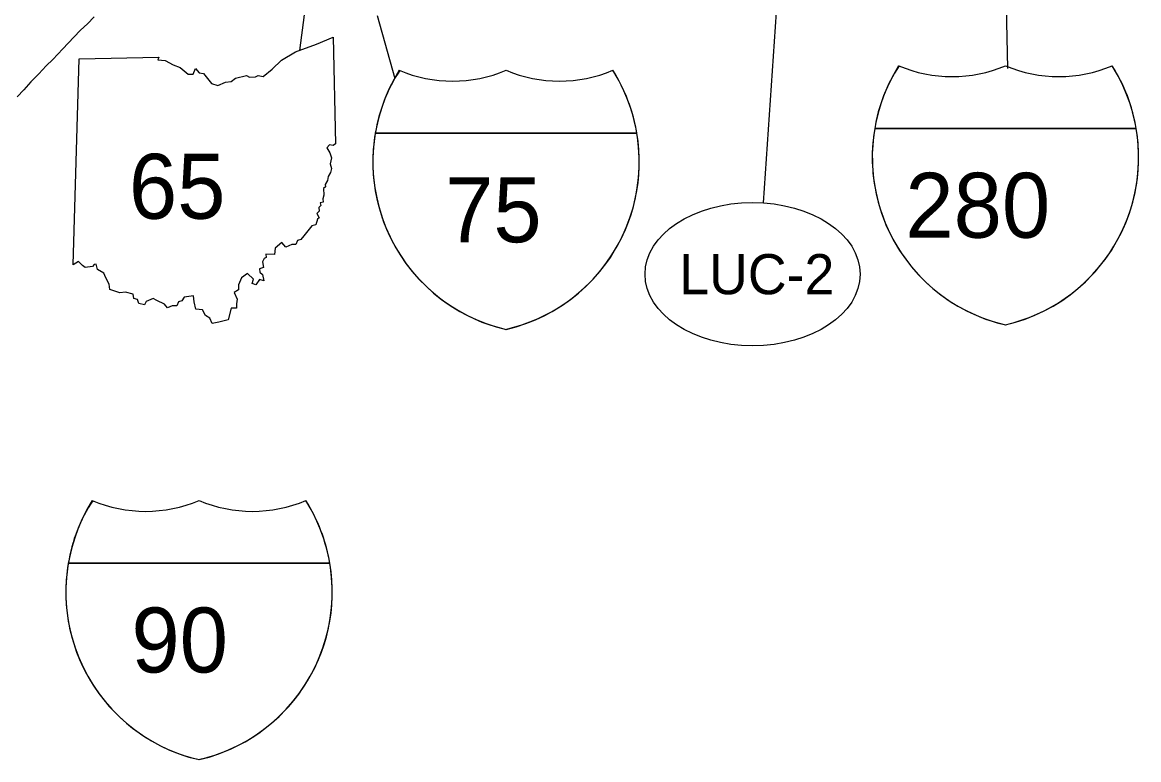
# Model space of a CAD drawing. Extents: x 0 to 750, y 0 to 507.
# Drawn here: x 327.4 to 405.3, y 183.7 to 235.1 of the extents above; entities that cross this region are included whole.
import ezdxf

# ---------------------------------------------------------------- set-up
doc = ezdxf.new("R2010")
doc.units = 0
for name, color, linetype in [('DV_X_Corp_Line', 7, 'Continuous'), ('GM_X_County', 7, 'Continuous'), ('GM_X_Interstate_Route', 7, 'Continuous'), ('GM_X_State_Route', 7, 'Continuous'), ('SH_Data', 7, 'Continuous')]:
    doc.layers.add(name, color=color, linetype=linetype)

msp = doc.modelspace()

# ---------------------------------------------------------------- linework, layer by layer
at = {"layer": 'DV_X_Corp_Line'}
msp.add_lwpolyline([(332.377, 235.528), (331.917, 235.045), (331.423, 234.597), (330.964, 234.113), (330.193, 233.304), (329.498, 232.548), (329.044, 232.12), (328.518, 231.557), (327.972, 231.005), (327.486, 230.432), (327.021, 229.948)], dxfattribs=at)
at = {"layer": 'GM_X_County'}
msp.add_lwpolyline([(332.377, 235.528), (331.917, 235.045), (331.423, 234.597), (330.964, 234.113), (330.193, 233.304), (329.498, 232.548), (329.044, 232.12), (328.518, 231.557), (327.972, 231.005), (327.486, 230.432), (327.021, 229.948)], dxfattribs=at)
at = {"layer": 'GM_X_Interstate_Route'}
for p, q in [((352.129, 235.628), (353.35, 231.223)), ((330.932, 218.25), (331.334, 232.613)), ((330.932, 218.25), (331.334, 232.613)), ((352, 227.428), (370.243, 227.428)), ((370.243, 227.428), (352, 227.428)), ((370.243, 227.428), (352, 227.428)), ((386.836, 227.744), (405.08, 227.744)), ((405.08, 227.744), (386.836, 227.744)), ((405.08, 227.744), (386.836, 227.744)), ((330.582, 197.435), (348.826, 197.435)), ((348.826, 197.435), (330.582, 197.435)), ((348.826, 197.435), (330.582, 197.435))]:
    msp.add_line(p, q, dxfattribs=at)
for points in [[(396.112, 231.926), (396.028, 236.226), (396.022, 237.332), (396.046, 239.165), (396.064, 241.773), (396.025, 242.916), (395.902, 243.544), (395.699, 244.12), (395.397, 244.737), (394.792, 245.558), (394.55, 245.776), (393.954, 246.268), (392.983, 246.764), (391.574, 247.402), (390.882, 247.742), (390.272, 248.041), (389.689, 248.355), (389.281, 248.609), (388.743, 249.023), (388.14, 249.62), (387.625, 250.251), (387.093, 251.051), (386.285, 252.327)], [(331.334, 232.613), (336.906, 232.707), (336.819, 232.533), (337.345, 232.497), (337.904, 232.19), (338.376, 231.996), (338.954, 231.539), (339.3, 231.544), (339.446, 231.919), (339.711, 231.63), (340.025, 231.578), (340.568, 230.891), (341.017, 230.742), (341.554, 230.978), (341.955, 231.016), (342.248, 231.249), (343.013, 231.448), (343.227, 231.329), (343.631, 231.353), (343.835, 231.441), (344.188, 231.363), (344.81, 231.885), (345.45, 232.501), (346.434, 233.082), (347.904, 233.632), (349.066, 234.124), (349.234, 226.671)], [(331.334, 232.613), (336.906, 232.707), (336.819, 232.533), (337.345, 232.497), (337.904, 232.19), (338.376, 231.996), (338.954, 231.539), (339.3, 231.544), (339.446, 231.919), (339.711, 231.63), (340.025, 231.578), (340.568, 230.891), (341.017, 230.742), (341.554, 230.978), (341.955, 231.016), (342.248, 231.249), (343.013, 231.448), (343.227, 231.329), (343.631, 231.353), (343.835, 231.441), (344.188, 231.363), (344.81, 231.885), (345.45, 232.501), (346.434, 233.082), (347.904, 233.632), (349.066, 234.124), (349.234, 226.671)], [(349.234, 226.671), (349.063, 226.566), (348.796, 226.615), (348.616, 226.406), (348.838, 226.058), (348.943, 225.689), (348.85, 225.283), (348.942, 224.948), (348.88, 224.668), (348.712, 224.389), (348.654, 224.122), (348.511, 223.842), (348.523, 223.685), (348.387, 223.561), (348.412, 223.095), (348.343, 222.837), (348.366, 222.614), (348.146, 222.555), (348.196, 222.371), (348.056, 222.229), (348.086, 221.984), (347.927, 221.828), (348.081, 221.516), (347.957, 221.416), (347.854, 221.036), (347.571, 220.959), (347.005, 220.263), (346.805, 220.001), (346.58, 219.935), (346.456, 219.665), (346.18, 219.664), (345.761, 219.477), (345.49, 219.799), (345.016, 219.411), (344.962, 218.963), (344.362, 218.978), (344.386, 218.751), (344.252, 218.685), (344.13, 218.458), (344.201, 218.055), (343.92, 217.953), (343.954, 217.718), (344.134, 217.575), (344.214, 217.128), (343.915, 217.219), (343.671, 216.842), (343.42, 216.93), (343.502, 217.25), (343.078, 217.634), (342.676, 217.326), (342.466, 216.835), (342.464, 216.504), (342.165, 216.304), (342.357, 215.837), (342.322, 215.515), (342.327, 215.21), (341.953, 215.221), (341.727, 214.396)], [(349.234, 226.671), (349.063, 226.566), (348.796, 226.615), (348.616, 226.406), (348.838, 226.058), (348.943, 225.689), (348.85, 225.283), (348.942, 224.948), (348.88, 224.668), (348.712, 224.389), (348.654, 224.122), (348.511, 223.842), (348.523, 223.685), (348.387, 223.561), (348.412, 223.095), (348.343, 222.837), (348.366, 222.614), (348.146, 222.555), (348.196, 222.371), (348.056, 222.229), (348.086, 221.984), (347.927, 221.828), (348.081, 221.516), (347.957, 221.416), (347.854, 221.036), (347.571, 220.959), (347.005, 220.263), (346.805, 220.001), (346.58, 219.935), (346.456, 219.665), (346.18, 219.664), (345.761, 219.477), (345.49, 219.799), (345.016, 219.411), (344.962, 218.963), (344.362, 218.978), (344.386, 218.751), (344.252, 218.685), (344.13, 218.458), (344.201, 218.055), (343.92, 217.953), (343.954, 217.718), (344.134, 217.575), (344.214, 217.128), (343.915, 217.219), (343.671, 216.842), (343.42, 216.93), (343.502, 217.25), (343.078, 217.634), (342.676, 217.326), (342.466, 216.835), (342.464, 216.504), (342.165, 216.304), (342.357, 215.837), (342.322, 215.515), (342.327, 215.21), (341.953, 215.221), (341.727, 214.396)], [(341.727, 214.396), (341.076, 214.238), (340.625, 214.144), (340.466, 214.519), (340.143, 214.716), (339.933, 215.093), (339.469, 215.145), (339.359, 215.662), (339.308, 216.083), (338.674, 215.979), (338.5, 215.722), (338.275, 215.653), (338.144, 215.394), (337.838, 215.373), (337.509, 215.25), (337.294, 215.504), (336.755, 215.759), (336.513, 215.891), (336.007, 215.686), (335.899, 215.445), (335.496, 215.551), (335.401, 215.821), (335.157, 215.902), (335.103, 216.188), (334.582, 216.34), (334.183, 216.28), (333.48, 216.51), (333.437, 216.886), (333.197, 217.345), (333.072, 217.664), (332.627, 217.907), (332.537, 218.285), (332.395, 218.274), (332.265, 218.12), (331.771, 218.05), (331.574, 218.205), (331.297, 218.469), (330.932, 218.25)], [(341.727, 214.396), (341.076, 214.238), (340.625, 214.144), (340.466, 214.519), (340.143, 214.716), (339.933, 215.093), (339.469, 215.145), (339.359, 215.662), (339.308, 216.083), (338.674, 215.979), (338.5, 215.722), (338.275, 215.653), (338.144, 215.394), (337.838, 215.373), (337.509, 215.25), (337.294, 215.504), (336.755, 215.759), (336.513, 215.891), (336.007, 215.686), (335.899, 215.445), (335.496, 215.551), (335.401, 215.821), (335.157, 215.902), (335.103, 216.188), (334.582, 216.34), (334.183, 216.28), (333.48, 216.51), (333.437, 216.886), (333.197, 217.345), (333.072, 217.664), (332.627, 217.907), (332.537, 218.285), (332.395, 218.274), (332.265, 218.12), (331.771, 218.05), (331.574, 218.205), (331.297, 218.469), (330.932, 218.25)]]:
    msp.add_lwpolyline(points, dxfattribs=at)
for centre, radius, start, end in [((398.656, 225.735), 11.99, 147.82161, 256.99413), ((397.907, 225.943), 11.216, 146.65397, 170.75899), ((392.234, 240.932), 9.567, 247.08482, 292.91053), ((392.234, 240.932), 9.567, 247.08482, 292.91053), ((393.26, 225.735), 11.989, 283.00654, 32.17868), ((399.683, 240.934), 9.569, 247.09162, 292.90836), ((399.683, 240.934), 9.569, 247.09162, 292.90836), ((393.26, 225.735), 11.99, 9.64753, 32.17902), ((363.82, 225.418), 11.99, 147.82161, 256.99413), ((363.07, 225.626), 11.216, 146.65397, 170.75899), ((357.397, 240.616), 9.567, 247.08482, 292.91053), ((357.397, 240.616), 9.567, 247.08482, 292.91053), ((358.423, 225.418), 11.989, 283.00654, 32.17868), ((364.846, 240.618), 9.569, 247.09162, 292.90836), ((364.846, 240.618), 9.569, 247.09162, 292.90836), ((358.423, 225.418), 11.99, 9.64753, 32.17902), ((363.819, 225.418), 11.989, 170.35136, 256.9967), ((358.448, 225.414), 11.966, 282.76665, 9.68983), ((398.656, 225.734), 11.989, 170.35136, 256.9967), ((393.284, 225.73), 11.966, 282.76665, 9.68983), ((342.402, 195.426), 11.99, 147.82161, 256.99413), ((341.653, 195.634), 11.216, 146.65397, 170.75899), ((335.98, 210.623), 9.567, 247.08482, 292.91053), ((335.98, 210.623), 9.567, 247.08482, 292.91053), ((337.006, 195.426), 11.989, 283.00654, 32.17868), ((343.429, 210.625), 9.569, 247.09162, 292.90836), ((343.429, 210.625), 9.569, 247.09162, 292.90836), ((337.005, 195.426), 11.99, 9.64753, 32.17902), ((342.402, 195.426), 11.989, 170.35136, 256.9967), ((337.03, 195.421), 11.966, 282.76665, 9.68983)]:
    msp.add_arc(centre, radius, start, end, dxfattribs=at)
at = {"layer": 'GM_X_State_Route'}
msp.add_line((347.03, 235.67), (346.714, 233.187), dxfattribs=at)
at = {"layer": 'SH_Data'}
msp.add_line((379.083, 222.564), (381.621, 259.801), dxfattribs=at)
msp.add_ellipse((378.32, 217.59), major_axis=(7.5, 0), ratio=0.666667, dxfattribs=at)

# ---------------------------------------------------------------- texts
at = {"layer": 'GM_X_Interstate_Route'}
for s, p in [('65', (334.812, 221.453)), ('75', (356.867, 219.813)), ('280', (388.976, 220.13)), ('90', (334.986, 189.821))]:
    msp.add_text(s, height=4.5281, dxfattribs=at).set_placement(p)
at = {"layer": 'SH_Data'}
msp.add_text('LUC-2', height=2.8, dxfattribs=at).set_placement((373.2, 216.19))

doc.saveas('drawing.dxf')
